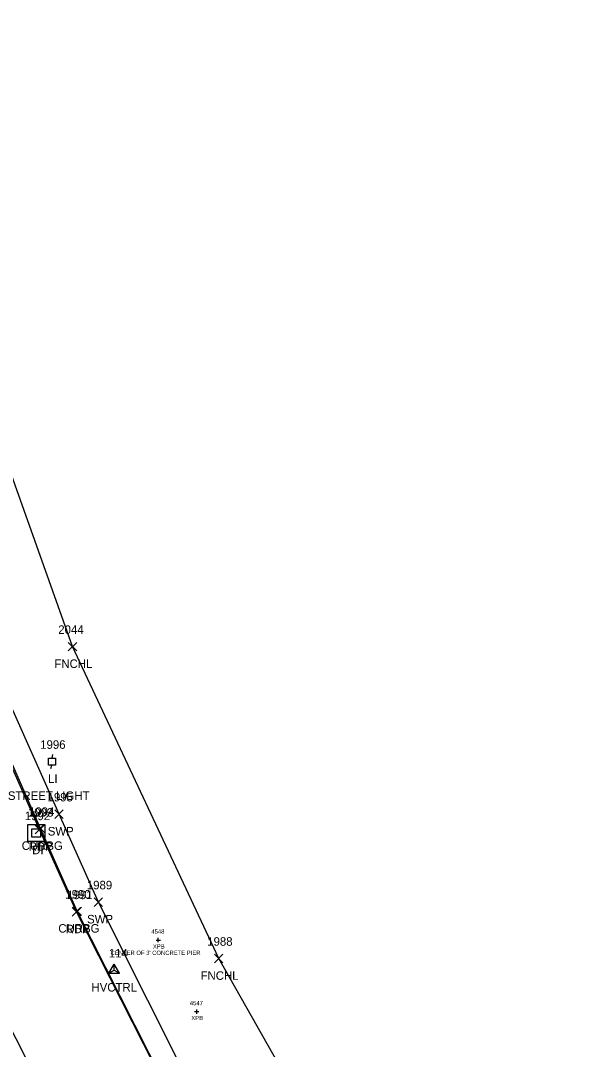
# Model space of a CAD drawing. Extents: x 1690689 to 1696275, y 438760 to 444007.
# Drawn here: x 1691598.9 to 1691729.4, y 439613.2 to 439854.7 of the extents above; entities that cross this region are included whole.
import ezdxf

# ---------------------------------------------------------------- set-up
doc = ezdxf.new("R2010")
doc.units = 0
for name, color, linetype in [('B_A', 7, 'Continuous'), ('B_C', 7, 'Continuous'), ('B_I', 7, 'Continuous'), ('B_TIC', 7, 'Continuous'), ('C_A', 7, 'Continuous'), ('C_I', 7, 'Continuous'), ('CPSM', 7, 'Continuous'), ('D_A', 7, 'Continuous'), ('D_I', 7, 'Continuous'), ('DS', 7, 'Continuous'), ('L_A', 7, 'Continuous'), ('L_I', 7, 'Continuous'), ('L_TIC', 7, 'Continuous'), ('LFNC', 7, 'Continuous'), ('P_A', 7, 'Continuous'), ('P_I', 7, 'Continuous'), ('P_TIC', 7, 'Continuous'), ('PET', 7, 'Continuous'), ('R_A', 7, 'Continuous'), ('R_I', 7, 'Continuous'), ('R_TIC', 7, 'Continuous'), ('RC', 7, 'Continuous'), ('RSW', 7, 'Continuous'), ('U_A', 7, 'Continuous'), ('U_C', 7, 'Continuous'), ('U_I', 7, 'Continuous'), ('ULP', 7, 'Continuous')]:
    doc.layers.add(name, color=color, linetype=linetype)

msp = doc.modelspace()

# ---------------------------------------------------------------- linework, layer by layer
at = {"layer": 'B_TIC'}
for p, q in [((1691631.25, 439638.9), (1691631.33, 439638.9)), ((1691640.28, 439622.1), (1691640.35, 439622.1))]:
    msp.add_line(p, q, dxfattribs=at)
for points in [[(1691630.75, 439638.9), (1691631.75, 439638.9)], [(1691631.25, 439638.4), (1691631.25, 439639.4)], [(1691639.78, 439622.1), (1691640.78, 439622.1)], [(1691640.28, 439621.6), (1691640.28, 439622.6)]]:
    msp.add_lwpolyline(points, dxfattribs=at)
at = {"layer": 'CPSM'}
for p, q in [((1691619.61, 439631.09), (1691620.86, 439633.25)), ((1691619.61, 439631.09), (1691620.86, 439631.81)), ((1691622.11, 439631.09), (1691620.86, 439633.25)), ((1691620.86, 439631.81), (1691620.86, 439633.25)), ((1691620.86, 439631.81), (1691620.86, 439631.81)), ((1691620.86, 439631.81), (1691622.11, 439631.09)), ((1691619.61, 439631.09), (1691622.11, 439631.09))]:
    msp.add_line(p, q, dxfattribs=at)
at = {"layer": 'DS'}
for p, q in [((1691600.58, 439666.03), (1691604.58, 439666.03)), ((1691600.58, 439662.03), (1691600.58, 439666.03)), ((1691604.58, 439666.03), (1691604.58, 439662.03)), ((1691601.58, 439663.03), (1691601.58, 439665.03)), ((1691601.58, 439665.03), (1691603.58, 439665.03)), ((1691603.58, 439663.03), (1691601.58, 439663.03)), ((1691602.59, 439664.04), (1691602.59, 439664.04)), ((1691602.59, 439664.04), (1691602.59, 439664.04)), ((1691603.58, 439665.03), (1691603.58, 439663.03)), ((1691604.58, 439662.03), (1691600.58, 439662.03))]:
    msp.add_line(p, q, dxfattribs=at)
at = {"layer": 'L_TIC'}
for points in [[(1691610.1, 439706.77), (1691612.1, 439708.77)], [(1691612.1, 439706.77), (1691610.1, 439708.77)], [(1691644.43, 439633.56), (1691646.43, 439635.56)], [(1691646.43, 439633.56), (1691644.43, 439635.56)]]:
    msp.add_lwpolyline(points, dxfattribs=at)
at = {"layer": 'LFNC'}
msp.add_lwpolyline([(1691807.26, 439412.53), (1691787.48, 439430.41), (1691771.88, 439447.07), (1691690.47, 439555.17), (1691645.43, 439634.56), (1691611.1, 439707.77), (1691582.01, 439789.5), (1691566.71, 439848.94), (1691556.2, 439899.11), (1691546, 439958.42), (1691528.18, 440069.26), (1691515.01, 440157.78), (1691504.49, 440231.44), (1691500.26, 440300.18), (1691503.51, 440349.74)], dxfattribs=at)
at = {"layer": 'P_TIC'}
for points in [[(1691602.32, 439663.85), (1691604.32, 439665.85)], [(1691604.32, 439663.85), (1691602.32, 439665.85)], [(1691611.01, 439644.5), (1691613.01, 439646.5)], [(1691613.01, 439644.5), (1691611.01, 439646.5)]]:
    msp.add_lwpolyline(points, dxfattribs=at)
at = {"layer": 'PET'}
for points in [[(1691740.86, 439438.42), (1691718.35, 439466.84), (1691694.57, 439500.54), (1691675.33, 439530.25), (1691660.2, 439555.16), (1691635.67, 439598.99), (1691612.01, 439645.5), (1691603.32, 439664.85), (1691590.17, 439694.4), (1691572.17, 439740.64), (1691559.21, 439778.61), (1691539.62, 439845.89), (1691529.44, 439889.89), (1691519.24, 439952.46), (1691514.72, 439998.23), (1691509.81, 440041.51), (1691505.13, 440074.25), (1691498.69, 440110.55), (1691490.49, 440154.58), (1691477, 440226.52), (1691464.62, 440293.86), (1691463.24, 440308.16), (1691465.2, 440320.4), (1691467.78, 440327.44)], [(1691744.74, 439390.57), (1691724.01, 439416.58), (1691689.24, 439462.55), (1691667.79, 439493.81), (1691647.49, 439525.62), (1691624.8, 439564.87), (1691610.1, 439591.66), (1691592.95, 439625.24), (1691579.41, 439654.32), (1691570.47, 439674.98), (1691555.57, 439711.44), (1691542.52, 439747.08), (1691524.14, 439803.51), (1691505.35, 439875.13)]]:
    msp.add_lwpolyline(points, dxfattribs=at)
at = {"layer": 'R_TIC'}
for points in [[(1691606.94, 439667.44), (1691608.94, 439669.44)], [(1691608.94, 439667.44), (1691606.94, 439669.44)], [(1691602.6, 439664.06), (1691604.6, 439666.06)], [(1691604.6, 439664.06), (1691602.6, 439666.06)], [(1691616.17, 439646.8), (1691618.17, 439648.8)], [(1691618.17, 439646.8), (1691616.17, 439648.8)], [(1691611.19, 439644.64), (1691613.19, 439646.64)], [(1691613.19, 439644.64), (1691611.19, 439646.64)]]:
    msp.add_lwpolyline(points, dxfattribs=at)
at = {"layer": 'RC'}
msp.add_lwpolyline([(1691743.99, 439435.22), (1691718.62, 439466.95), (1691694.8, 439500.79), (1691675.53, 439530.26), (1691660.54, 439555.5), (1691635.86, 439598.93), (1691612.19, 439645.64), (1691603.6, 439665.06), (1691590.6, 439694.56), (1691572.56, 439740.45), (1691559.42, 439778.8), (1691539.86, 439846.17), (1691529.78, 439890.1), (1691519.48, 439952.64), (1691515.02, 439998.4), (1691510.19, 440041.43), (1691505.45, 440074.27), (1691499.01, 440110.77), (1691490.99, 440154.57), (1691477.35, 440226.5), (1691464.87, 440293.92), (1691463.63, 440308.17), (1691465.44, 440320.36), (1691468.18, 440327.32)], dxfattribs=at)
at = {"layer": 'RSW'}
msp.add_lwpolyline([(1691747.52, 439438.86), (1691722.59, 439470.19), (1691699.11, 439503.91), (1691679.91, 439533.13), (1691665.02, 439557.93), (1691640.34, 439601.62), (1691617.17, 439647.8), (1691607.94, 439668.44), (1691595.18, 439697.07), (1691577.57, 439742.18), (1691564.36, 439780.44), (1691544.71, 439847.37), (1691534.58, 439891.31), (1691524.44, 439952.98), (1691520.21, 439998.63), (1691515.22, 440042.14), (1691510.39, 440075.19), (1691503.94, 440111.92), (1691496.05, 440155.61), (1691482.56, 440227.35), (1691469.87, 440294.77), (1691468.99, 440308.08), (1691470.09, 440318.44), (1691465.44, 440320.36)], dxfattribs=at)
at = {"layer": 'ULP'}
for p, q in [((1691606.43, 439682.46), (1691606.27, 439681.63)), ((1691605.43, 439679.96), (1691605.43, 439681.63)), ((1691605.43, 439681.63), (1691607.1, 439681.63)), ((1691607.1, 439679.96), (1691605.43, 439679.96)), ((1691606.02, 439679.13), (1691606.27, 439679.96)), ((1691606.27, 439680.79), (1691606.27, 439680.79)), ((1691607.1, 439681.63), (1691607.1, 439679.96))]:
    msp.add_line(p, q, dxfattribs=at)

# ---------------------------------------------------------------- texts
at = {"layer": 'B_A'}
for p in [(1691629.99, 439636.9), (1691639.01, 439620.1)]:
    msp.add_text('XPB', height=1, dxfattribs=at).set_placement(p)
at = {"layer": 'B_C'}
msp.add_text("CENTER OF 3' CONCRETE PIER", height=1, dxfattribs=at).set_placement((1691620.04, 439635.4))
at = {"layer": 'B_I'}
for s, p in [('4548', (1691629.62, 439640.4)), ('4547', (1691638.65, 439623.6))]:
    msp.add_text(s, height=1, dxfattribs=at).set_placement(p)
at = {"layer": 'C_A'}
msp.add_text('HVCTRL', height=2, dxfattribs=at).set_placement((1691615.56, 439626.81))
at = {"layer": 'C_I'}
msp.add_text('114', height=2, dxfattribs=at).set_placement((1691619.63, 439634.81))
at = {"layer": 'D_A'}
msp.add_text('DI', height=2, dxfattribs=at).set_placement((1691601.64, 439659.04))
at = {"layer": 'D_I'}
msp.add_text('1992', height=2, dxfattribs=at).set_placement((1691599.89, 439667.04))
at = {"layer": 'L_A'}
for p in [(1691606.85, 439702.77), (1691641.18, 439629.56)]:
    msp.add_text('FNCHL', height=2, dxfattribs=at).set_placement(p)
at = {"layer": 'L_I'}
for s, p in [('2044', (1691607.76, 439710.77)), ('1988', (1691642.74, 439637.56))]:
    msp.add_text(s, height=2, dxfattribs=at).set_placement(p)
at = {"layer": 'P_A'}
for p in [(1691600.81, 439659.85), (1691609.5, 439640.5)]:
    msp.add_text('RDP', height=2, dxfattribs=at).set_placement(p)
at = {"layer": 'P_I'}
for s, p in [('1993', (1691600.63, 439667.85)), ('1991', (1691609.88, 439648.5))]:
    msp.add_text(s, height=2, dxfattribs=at).set_placement(p)
at = {"layer": 'R_A'}
for s, p in [('SWP', (1691605.3, 439663.44)), ('CURBG', (1691599.18, 439660.06)), ('SWP', (1691614.53, 439642.8)), ('CURBG', (1691607.78, 439640.64))]:
    msp.add_text(s, height=2, dxfattribs=at).set_placement(p)
at = {"layer": 'R_I'}
for s, p in [('1995', (1691605.25, 439671.44)), ('1994', (1691600.91, 439668.06)), ('1989', (1691614.47, 439650.8)), ('1990', (1691609.41, 439648.64))]:
    msp.add_text(s, height=2, dxfattribs=at).set_placement(p)
at = {"layer": 'U_A'}
msp.add_text('LI', height=2, dxfattribs=at).set_placement((1691605.37, 439675.79))
at = {"layer": 'U_C'}
msp.add_text('STREET LIGHT', height=2, dxfattribs=at).set_placement((1691595.93, 439671.79))
at = {"layer": 'U_I'}
msp.add_text('1996', height=2, dxfattribs=at).set_placement((1691603.52, 439683.79))

doc.saveas('drawing.dxf')
